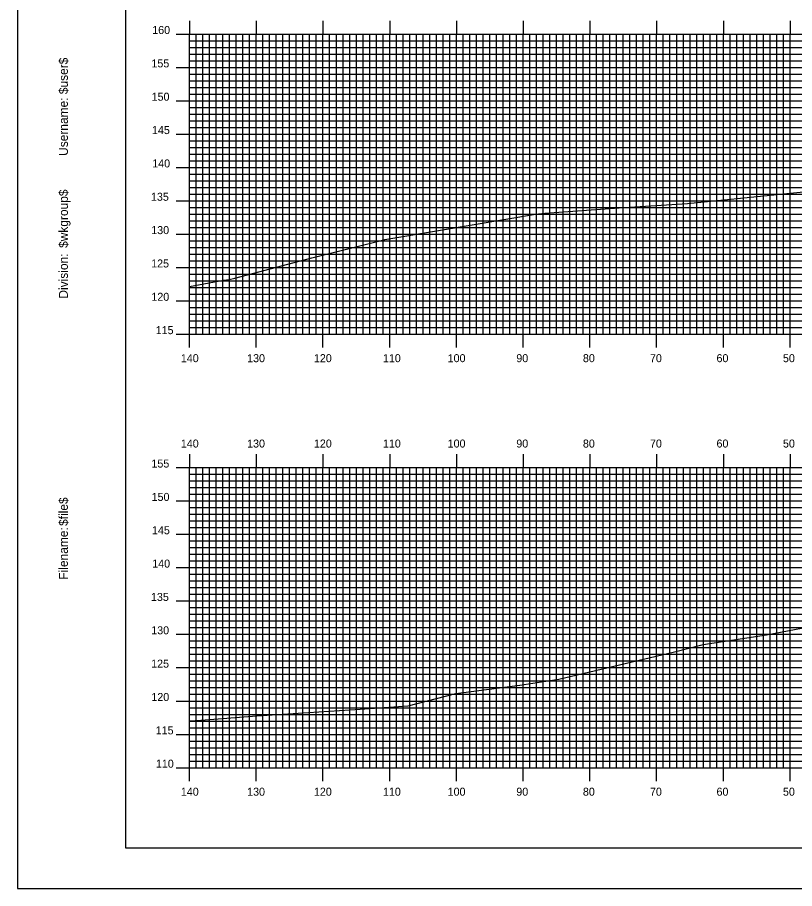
# Model space of a CAD drawing. Extents: x 1782647 to 1782990, y 442591 to 442811.
# Drawn here: x 1782647.2 to 1782763.6, y 442590.5 to 442721.2 of the extents above; entities that cross this region are included whole.
import ezdxf

# ---------------------------------------------------------------- set-up
doc = ezdxf.new("R2010")
doc.units = 0
for name, color, linetype in [('BORDER', 7, 'Continuous'), ('H_V ANNOTATION', 7, 'Continuous'), ('MAJOR', 7, 'Continuous'), ('MINOR', 7, 'Continuous'), ('PLOT BOUNDARY', 7, 'Continuous'), ('S_Roadway_Centerline', 7, 'Continuous')]:
    doc.layers.add(name, color=color, linetype=linetype)

msp = doc.modelspace()

# ---------------------------------------------------------------- linework, layer by layer
at = {"layer": 'BORDER'}
msp.add_lwpolyline([(1782663.35, 442596.67), (1782983.35, 442596.67), (1782983.35, 442806.67), (1782663.35, 442806.67)], close=True, dxfattribs=at)
at = {"layer": 'MAJOR'}
for p, q in [((1782672.95, 442720.67), (1782672.95, 442718.67)), ((1782682.95, 442720.67), (1782682.95, 442718.67)), ((1782692.95, 442720.67), (1782692.95, 442718.67)), ((1782702.95, 442720.67), (1782702.95, 442718.67)), ((1782712.95, 442720.67), (1782712.95, 442718.67)), ((1782722.95, 442720.67), (1782722.95, 442718.67)), ((1782732.95, 442720.67), (1782732.95, 442718.67)), ((1782742.95, 442720.67), (1782742.95, 442718.67)), ((1782752.95, 442720.67), (1782752.95, 442718.67)), ((1782762.95, 442720.67), (1782762.95, 442718.67)), ((1782670.94, 442718.67), (1782672.95, 442718.67)), ((1782672.95, 442718.67), (1782952.95, 442718.67)), ((1782672.95, 442673.67), (1782672.95, 442718.67)), ((1782672.95, 442673.67), (1782672.95, 442718.67)), ((1782672.95, 442718.67), (1782952.95, 442718.67)), ((1782682.95, 442673.67), (1782682.95, 442718.67)), ((1782692.95, 442673.67), (1782692.95, 442718.67)), ((1782702.95, 442673.67), (1782702.95, 442718.67)), ((1782712.95, 442673.67), (1782712.95, 442718.67)), ((1782722.95, 442673.67), (1782722.95, 442718.67)), ((1782732.95, 442673.67), (1782732.95, 442718.67)), ((1782742.95, 442673.67), (1782742.95, 442718.67)), ((1782752.95, 442673.67), (1782752.95, 442718.67)), ((1782762.95, 442673.67), (1782762.95, 442718.67)), ((1782670.94, 442713.67), (1782672.95, 442713.67)), ((1782672.95, 442713.67), (1782952.95, 442713.67)), ((1782670.94, 442708.67), (1782672.95, 442708.67)), ((1782672.95, 442708.67), (1782952.95, 442708.67)), ((1782670.94, 442703.67), (1782672.95, 442703.67)), ((1782672.95, 442703.67), (1782952.95, 442703.67)), ((1782670.94, 442698.67), (1782672.95, 442698.67)), ((1782672.95, 442698.67), (1782952.95, 442698.67)), ((1782670.94, 442693.67), (1782672.95, 442693.67)), ((1782672.95, 442693.67), (1782952.95, 442693.67)), ((1782670.94, 442688.67), (1782672.95, 442688.67)), ((1782672.95, 442688.67), (1782952.95, 442688.67)), ((1782670.94, 442683.67), (1782672.95, 442683.67)), ((1782672.95, 442683.67), (1782952.95, 442683.67)), ((1782670.94, 442678.67), (1782672.95, 442678.67)), ((1782672.95, 442678.67), (1782952.95, 442678.67)), ((1782670.94, 442673.67), (1782672.95, 442673.67)), ((1782672.95, 442673.67), (1782952.95, 442673.67)), ((1782672.95, 442673.67), (1782952.95, 442673.67)), ((1782672.95, 442671.66), (1782672.95, 442673.67)), ((1782682.95, 442671.66), (1782682.95, 442673.67)), ((1782692.95, 442671.66), (1782692.95, 442673.67)), ((1782702.95, 442671.66), (1782702.95, 442673.67)), ((1782712.95, 442671.66), (1782712.95, 442673.67)), ((1782722.95, 442671.66), (1782722.95, 442673.67)), ((1782732.95, 442671.66), (1782732.95, 442673.67)), ((1782742.95, 442671.66), (1782742.95, 442673.67)), ((1782752.95, 442671.66), (1782752.95, 442673.67)), ((1782762.95, 442671.66), (1782762.95, 442673.67)), ((1782672.95, 442655.67), (1782672.95, 442653.67)), ((1782682.95, 442655.67), (1782682.95, 442653.67)), ((1782692.95, 442655.67), (1782692.95, 442653.67)), ((1782702.95, 442655.67), (1782702.95, 442653.67)), ((1782712.95, 442655.67), (1782712.95, 442653.67)), ((1782722.95, 442655.67), (1782722.95, 442653.67)), ((1782732.95, 442655.67), (1782732.95, 442653.67)), ((1782742.95, 442655.67), (1782742.95, 442653.67)), ((1782752.95, 442655.67), (1782752.95, 442653.67)), ((1782762.95, 442655.67), (1782762.95, 442653.67)), ((1782670.94, 442653.67), (1782672.95, 442653.67)), ((1782672.95, 442653.67), (1782952.95, 442653.67)), ((1782672.95, 442608.67), (1782672.95, 442653.67)), ((1782672.95, 442608.67), (1782672.95, 442653.67)), ((1782672.95, 442653.67), (1782952.95, 442653.67)), ((1782682.95, 442608.67), (1782682.95, 442653.67)), ((1782692.95, 442608.67), (1782692.95, 442653.67)), ((1782702.95, 442608.67), (1782702.95, 442653.67)), ((1782712.95, 442608.67), (1782712.95, 442653.67)), ((1782722.95, 442608.67), (1782722.95, 442653.67)), ((1782732.95, 442608.67), (1782732.95, 442653.67)), ((1782742.95, 442608.67), (1782742.95, 442653.67)), ((1782752.95, 442608.67), (1782752.95, 442653.67)), ((1782762.95, 442608.67), (1782762.95, 442653.67)), ((1782670.94, 442648.67), (1782672.95, 442648.67)), ((1782672.95, 442648.67), (1782952.95, 442648.67)), ((1782670.94, 442643.67), (1782672.95, 442643.67)), ((1782672.95, 442643.67), (1782952.95, 442643.67)), ((1782670.94, 442638.67), (1782672.95, 442638.67)), ((1782672.95, 442638.67), (1782952.95, 442638.67)), ((1782670.94, 442633.67), (1782672.95, 442633.67)), ((1782672.95, 442633.67), (1782952.95, 442633.67)), ((1782670.94, 442628.67), (1782672.95, 442628.67)), ((1782672.95, 442628.67), (1782952.95, 442628.67)), ((1782670.94, 442623.67), (1782672.95, 442623.67)), ((1782672.95, 442623.67), (1782952.95, 442623.67)), ((1782670.94, 442618.67), (1782672.95, 442618.67)), ((1782672.95, 442618.67), (1782952.95, 442618.67)), ((1782670.94, 442613.67), (1782672.95, 442613.67)), ((1782672.95, 442613.67), (1782952.95, 442613.67)), ((1782670.94, 442608.67), (1782672.95, 442608.67)), ((1782672.95, 442608.67), (1782952.95, 442608.67)), ((1782672.95, 442608.67), (1782952.95, 442608.67)), ((1782672.95, 442606.66), (1782672.95, 442608.67)), ((1782682.95, 442606.66), (1782682.95, 442608.67)), ((1782692.95, 442606.66), (1782692.95, 442608.67)), ((1782702.95, 442606.66), (1782702.95, 442608.67)), ((1782712.95, 442606.66), (1782712.95, 442608.67)), ((1782722.95, 442606.66), (1782722.95, 442608.67)), ((1782732.95, 442606.66), (1782732.95, 442608.67)), ((1782742.95, 442606.66), (1782742.95, 442608.67)), ((1782752.95, 442606.66), (1782752.95, 442608.67)), ((1782762.95, 442606.66), (1782762.95, 442608.67))]:
    msp.add_line(p, q, dxfattribs=at)
at = {"layer": 'MINOR'}
for p, q in [((1782673.95, 442673.67), (1782673.95, 442718.67)), ((1782674.95, 442673.67), (1782674.95, 442718.67)), ((1782675.95, 442673.67), (1782675.95, 442718.67)), ((1782676.95, 442673.67), (1782676.95, 442718.67)), ((1782677.95, 442673.67), (1782677.95, 442718.67)), ((1782678.95, 442673.67), (1782678.95, 442718.67)), ((1782679.95, 442673.67), (1782679.95, 442718.67)), ((1782680.95, 442673.67), (1782680.95, 442718.67)), ((1782681.95, 442673.67), (1782681.95, 442718.67)), ((1782683.95, 442673.67), (1782683.95, 442718.67)), ((1782684.95, 442673.67), (1782684.95, 442718.67)), ((1782685.95, 442673.67), (1782685.95, 442718.67)), ((1782686.95, 442673.67), (1782686.95, 442718.67)), ((1782687.95, 442673.67), (1782687.95, 442718.67)), ((1782688.95, 442673.67), (1782688.95, 442718.67)), ((1782689.95, 442673.67), (1782689.95, 442718.67)), ((1782690.95, 442673.67), (1782690.95, 442718.67)), ((1782691.95, 442673.67), (1782691.95, 442718.67)), ((1782693.95, 442673.67), (1782693.95, 442718.67)), ((1782694.95, 442673.67), (1782694.95, 442718.67)), ((1782695.95, 442673.67), (1782695.95, 442718.67)), ((1782696.95, 442673.67), (1782696.95, 442718.67)), ((1782697.95, 442673.67), (1782697.95, 442718.67)), ((1782698.95, 442673.67), (1782698.95, 442718.67)), ((1782699.95, 442673.67), (1782699.95, 442718.67)), ((1782700.95, 442673.67), (1782700.95, 442718.67)), ((1782701.95, 442673.67), (1782701.95, 442718.67)), ((1782703.95, 442673.67), (1782703.95, 442718.67)), ((1782704.95, 442673.67), (1782704.95, 442718.67)), ((1782705.95, 442673.67), (1782705.95, 442718.67)), ((1782706.95, 442673.67), (1782706.95, 442718.67)), ((1782707.95, 442673.67), (1782707.95, 442718.67)), ((1782708.95, 442673.67), (1782708.95, 442718.67)), ((1782709.95, 442673.67), (1782709.95, 442718.67)), ((1782710.95, 442673.67), (1782710.95, 442718.67)), ((1782711.95, 442673.67), (1782711.95, 442718.67)), ((1782713.95, 442673.67), (1782713.95, 442718.67)), ((1782714.95, 442673.67), (1782714.95, 442718.67)), ((1782715.95, 442673.67), (1782715.95, 442718.67)), ((1782716.95, 442673.67), (1782716.95, 442718.67)), ((1782717.95, 442673.67), (1782717.95, 442718.67)), ((1782718.95, 442673.67), (1782718.95, 442718.67)), ((1782719.95, 442673.67), (1782719.95, 442718.67)), ((1782720.95, 442673.67), (1782720.95, 442718.67)), ((1782721.95, 442673.67), (1782721.95, 442718.67)), ((1782723.95, 442673.67), (1782723.95, 442718.67)), ((1782724.95, 442673.67), (1782724.95, 442718.67)), ((1782725.95, 442673.67), (1782725.95, 442718.67)), ((1782726.95, 442673.67), (1782726.95, 442718.67)), ((1782727.95, 442673.67), (1782727.95, 442718.67)), ((1782728.95, 442673.67), (1782728.95, 442718.67)), ((1782729.95, 442673.67), (1782729.95, 442718.67)), ((1782730.95, 442673.67), (1782730.95, 442718.67)), ((1782731.95, 442673.67), (1782731.95, 442718.67)), ((1782733.95, 442673.67), (1782733.95, 442718.67)), ((1782734.95, 442673.67), (1782734.95, 442718.67)), ((1782735.95, 442673.67), (1782735.95, 442718.67)), ((1782736.95, 442673.67), (1782736.95, 442718.67)), ((1782737.95, 442673.67), (1782737.95, 442718.67)), ((1782738.95, 442673.67), (1782738.95, 442718.67)), ((1782739.95, 442673.67), (1782739.95, 442718.67)), ((1782740.95, 442673.67), (1782740.95, 442718.67)), ((1782741.95, 442673.67), (1782741.95, 442718.67)), ((1782743.95, 442673.67), (1782743.95, 442718.67)), ((1782744.95, 442673.67), (1782744.95, 442718.67)), ((1782745.95, 442673.67), (1782745.95, 442718.67)), ((1782746.95, 442673.67), (1782746.95, 442718.67)), ((1782747.95, 442673.67), (1782747.95, 442718.67)), ((1782748.95, 442673.67), (1782748.95, 442718.67)), ((1782749.95, 442673.67), (1782749.95, 442718.67)), ((1782750.95, 442673.67), (1782750.95, 442718.67)), ((1782751.95, 442673.67), (1782751.95, 442718.67)), ((1782753.95, 442673.67), (1782753.95, 442718.67)), ((1782754.95, 442673.67), (1782754.95, 442718.67)), ((1782755.95, 442673.67), (1782755.95, 442718.67)), ((1782756.95, 442673.67), (1782756.95, 442718.67)), ((1782757.95, 442673.67), (1782757.95, 442718.67)), ((1782758.95, 442673.67), (1782758.95, 442718.67)), ((1782759.95, 442673.67), (1782759.95, 442718.67)), ((1782760.95, 442673.67), (1782760.95, 442718.67)), ((1782761.95, 442673.67), (1782761.95, 442718.67)), ((1782672.95, 442717.67), (1782952.95, 442717.67)), ((1782672.95, 442717.67), (1782674.95, 442717.67)), ((1782672.95, 442716.67), (1782952.95, 442716.67)), ((1782672.95, 442716.67), (1782674.95, 442716.67)), ((1782672.95, 442715.67), (1782952.95, 442715.67)), ((1782672.95, 442715.67), (1782674.95, 442715.67)), ((1782672.95, 442714.67), (1782952.95, 442714.67)), ((1782672.95, 442714.67), (1782674.95, 442714.67)), ((1782672.95, 442712.67), (1782952.95, 442712.67)), ((1782672.95, 442712.67), (1782674.95, 442712.67)), ((1782672.95, 442711.67), (1782952.95, 442711.67)), ((1782672.95, 442711.67), (1782674.95, 442711.67)), ((1782672.95, 442710.67), (1782952.95, 442710.67)), ((1782672.95, 442710.67), (1782674.95, 442710.67)), ((1782672.95, 442709.67), (1782952.95, 442709.67)), ((1782672.95, 442709.67), (1782674.95, 442709.67)), ((1782672.95, 442707.67), (1782952.95, 442707.67)), ((1782672.95, 442707.67), (1782674.95, 442707.67)), ((1782672.95, 442706.67), (1782952.95, 442706.67)), ((1782672.95, 442706.67), (1782674.95, 442706.67)), ((1782672.95, 442705.67), (1782952.95, 442705.67)), ((1782672.95, 442705.67), (1782674.95, 442705.67)), ((1782672.95, 442704.67), (1782952.95, 442704.67)), ((1782672.95, 442704.67), (1782674.95, 442704.67)), ((1782672.95, 442702.67), (1782952.95, 442702.67)), ((1782672.95, 442702.67), (1782674.95, 442702.67)), ((1782672.95, 442701.67), (1782952.95, 442701.67)), ((1782672.95, 442701.67), (1782674.95, 442701.67)), ((1782672.95, 442700.67), (1782952.95, 442700.67)), ((1782672.95, 442700.67), (1782674.95, 442700.67)), ((1782672.95, 442699.67), (1782952.95, 442699.67)), ((1782672.95, 442699.67), (1782674.95, 442699.67)), ((1782672.95, 442697.67), (1782952.95, 442697.67)), ((1782672.95, 442697.67), (1782674.95, 442697.67)), ((1782672.95, 442696.67), (1782952.95, 442696.67)), ((1782672.95, 442696.67), (1782674.95, 442696.67)), ((1782672.95, 442695.67), (1782952.95, 442695.67)), ((1782672.95, 442695.67), (1782674.95, 442695.67)), ((1782672.95, 442694.67), (1782952.95, 442694.67)), ((1782672.95, 442694.67), (1782674.95, 442694.67)), ((1782672.95, 442692.67), (1782952.95, 442692.67)), ((1782672.95, 442692.67), (1782674.95, 442692.67)), ((1782672.95, 442691.67), (1782952.95, 442691.67)), ((1782672.95, 442691.67), (1782674.95, 442691.67)), ((1782672.95, 442690.67), (1782952.95, 442690.67)), ((1782672.95, 442690.67), (1782674.95, 442690.67)), ((1782672.95, 442689.67), (1782952.95, 442689.67)), ((1782672.95, 442689.67), (1782674.95, 442689.67)), ((1782672.95, 442687.67), (1782952.95, 442687.67)), ((1782672.95, 442687.67), (1782674.95, 442687.67)), ((1782672.95, 442686.67), (1782952.95, 442686.67)), ((1782672.95, 442686.67), (1782674.95, 442686.67)), ((1782672.95, 442685.67), (1782952.95, 442685.67)), ((1782672.95, 442685.67), (1782674.95, 442685.67)), ((1782672.95, 442684.67), (1782952.95, 442684.67)), ((1782672.95, 442684.67), (1782674.95, 442684.67)), ((1782672.95, 442682.67), (1782952.95, 442682.67)), ((1782672.95, 442682.67), (1782674.95, 442682.67)), ((1782672.95, 442681.67), (1782952.95, 442681.67)), ((1782672.95, 442681.67), (1782674.95, 442681.67)), ((1782672.95, 442680.67), (1782952.95, 442680.67)), ((1782672.95, 442680.67), (1782674.95, 442680.67)), ((1782672.95, 442679.67), (1782952.95, 442679.67)), ((1782672.95, 442679.67), (1782674.95, 442679.67)), ((1782672.95, 442677.67), (1782952.95, 442677.67)), ((1782672.95, 442677.67), (1782674.95, 442677.67)), ((1782672.95, 442676.67), (1782952.95, 442676.67)), ((1782672.95, 442676.67), (1782674.95, 442676.67)), ((1782672.95, 442675.67), (1782952.95, 442675.67)), ((1782672.95, 442675.67), (1782674.95, 442675.67)), ((1782672.95, 442674.67), (1782952.95, 442674.67)), ((1782672.95, 442674.67), (1782674.95, 442674.67)), ((1782672.95, 442652.67), (1782952.95, 442652.67)), ((1782672.95, 442652.67), (1782674.95, 442652.67)), ((1782673.95, 442608.67), (1782673.95, 442653.67)), ((1782674.95, 442608.67), (1782674.95, 442653.67)), ((1782675.95, 442608.67), (1782675.95, 442653.67)), ((1782676.95, 442608.67), (1782676.95, 442653.67)), ((1782677.95, 442608.67), (1782677.95, 442653.67)), ((1782678.95, 442608.67), (1782678.95, 442653.67)), ((1782679.95, 442608.67), (1782679.95, 442653.67)), ((1782680.95, 442608.67), (1782680.95, 442653.67)), ((1782681.95, 442608.67), (1782681.95, 442653.67)), ((1782683.95, 442608.67), (1782683.95, 442653.67)), ((1782684.95, 442608.67), (1782684.95, 442653.67)), ((1782685.95, 442608.67), (1782685.95, 442653.67)), ((1782686.95, 442608.67), (1782686.95, 442653.67)), ((1782687.95, 442608.67), (1782687.95, 442653.67)), ((1782688.95, 442608.67), (1782688.95, 442653.67)), ((1782689.95, 442608.67), (1782689.95, 442653.67)), ((1782690.95, 442608.67), (1782690.95, 442653.67)), ((1782691.95, 442608.67), (1782691.95, 442653.67)), ((1782693.95, 442608.67), (1782693.95, 442653.67)), ((1782694.95, 442608.67), (1782694.95, 442653.67)), ((1782695.95, 442608.67), (1782695.95, 442653.67)), ((1782696.95, 442608.67), (1782696.95, 442653.67)), ((1782697.95, 442608.67), (1782697.95, 442653.67)), ((1782698.95, 442608.67), (1782698.95, 442653.67)), ((1782699.95, 442608.67), (1782699.95, 442653.67)), ((1782700.95, 442608.67), (1782700.95, 442653.67)), ((1782701.95, 442608.67), (1782701.95, 442653.67)), ((1782703.95, 442608.67), (1782703.95, 442653.67)), ((1782704.95, 442608.67), (1782704.95, 442653.67)), ((1782705.95, 442608.67), (1782705.95, 442653.67)), ((1782706.95, 442608.67), (1782706.95, 442653.67)), ((1782707.95, 442608.67), (1782707.95, 442653.67)), ((1782708.95, 442608.67), (1782708.95, 442653.67)), ((1782709.95, 442608.67), (1782709.95, 442653.67)), ((1782710.95, 442608.67), (1782710.95, 442653.67)), ((1782711.95, 442608.67), (1782711.95, 442653.67)), ((1782713.95, 442608.67), (1782713.95, 442653.67)), ((1782714.95, 442608.67), (1782714.95, 442653.67)), ((1782715.95, 442608.67), (1782715.95, 442653.67)), ((1782716.95, 442608.67), (1782716.95, 442653.67)), ((1782717.95, 442608.67), (1782717.95, 442653.67)), ((1782718.95, 442608.67), (1782718.95, 442653.67)), ((1782719.95, 442608.67), (1782719.95, 442653.67)), ((1782720.95, 442608.67), (1782720.95, 442653.67)), ((1782721.95, 442608.67), (1782721.95, 442653.67)), ((1782723.95, 442608.67), (1782723.95, 442653.67)), ((1782724.95, 442608.67), (1782724.95, 442653.67)), ((1782725.95, 442608.67), (1782725.95, 442653.67)), ((1782726.95, 442608.67), (1782726.95, 442653.67)), ((1782727.95, 442608.67), (1782727.95, 442653.67)), ((1782728.95, 442608.67), (1782728.95, 442653.67)), ((1782729.95, 442608.67), (1782729.95, 442653.67)), ((1782730.95, 442608.67), (1782730.95, 442653.67)), ((1782731.95, 442608.67), (1782731.95, 442653.67)), ((1782733.95, 442608.67), (1782733.95, 442653.67)), ((1782734.95, 442608.67), (1782734.95, 442653.67)), ((1782735.95, 442608.67), (1782735.95, 442653.67)), ((1782736.95, 442608.67), (1782736.95, 442653.67)), ((1782737.95, 442608.67), (1782737.95, 442653.67)), ((1782738.95, 442608.67), (1782738.95, 442653.67)), ((1782739.95, 442608.67), (1782739.95, 442653.67)), ((1782740.95, 442608.67), (1782740.95, 442653.67)), ((1782741.95, 442608.67), (1782741.95, 442653.67)), ((1782743.95, 442608.67), (1782743.95, 442653.67)), ((1782744.95, 442608.67), (1782744.95, 442653.67)), ((1782745.95, 442608.67), (1782745.95, 442653.67)), ((1782746.95, 442608.67), (1782746.95, 442653.67)), ((1782747.95, 442608.67), (1782747.95, 442653.67)), ((1782748.95, 442608.67), (1782748.95, 442653.67)), ((1782749.95, 442608.67), (1782749.95, 442653.67)), ((1782750.95, 442608.67), (1782750.95, 442653.67)), ((1782751.95, 442608.67), (1782751.95, 442653.67)), ((1782753.95, 442608.67), (1782753.95, 442653.67)), ((1782754.95, 442608.67), (1782754.95, 442653.67)), ((1782755.95, 442608.67), (1782755.95, 442653.67)), ((1782756.95, 442608.67), (1782756.95, 442653.67)), ((1782757.95, 442608.67), (1782757.95, 442653.67)), ((1782758.95, 442608.67), (1782758.95, 442653.67)), ((1782759.95, 442608.67), (1782759.95, 442653.67)), ((1782760.95, 442608.67), (1782760.95, 442653.67)), ((1782761.95, 442608.67), (1782761.95, 442653.67)), ((1782672.95, 442651.67), (1782952.95, 442651.67)), ((1782672.95, 442651.67), (1782674.95, 442651.67)), ((1782672.95, 442650.67), (1782952.95, 442650.67)), ((1782672.95, 442650.67), (1782674.95, 442650.67)), ((1782672.95, 442649.67), (1782952.95, 442649.67)), ((1782672.95, 442649.67), (1782674.95, 442649.67)), ((1782672.95, 442647.67), (1782952.95, 442647.67)), ((1782672.95, 442647.67), (1782674.95, 442647.67)), ((1782672.95, 442646.67), (1782952.95, 442646.67)), ((1782672.95, 442646.67), (1782674.95, 442646.67)), ((1782672.95, 442645.67), (1782952.95, 442645.67)), ((1782672.95, 442645.67), (1782674.95, 442645.67)), ((1782672.95, 442644.67), (1782952.95, 442644.67)), ((1782672.95, 442644.67), (1782674.95, 442644.67)), ((1782672.95, 442642.67), (1782952.95, 442642.67)), ((1782672.95, 442642.67), (1782674.95, 442642.67)), ((1782672.95, 442641.67), (1782952.95, 442641.67)), ((1782672.95, 442641.67), (1782674.95, 442641.67)), ((1782672.95, 442640.67), (1782952.95, 442640.67)), ((1782672.95, 442640.67), (1782674.95, 442640.67)), ((1782672.95, 442639.67), (1782952.95, 442639.67)), ((1782672.95, 442639.67), (1782674.95, 442639.67)), ((1782672.95, 442637.67), (1782952.95, 442637.67)), ((1782672.95, 442637.67), (1782674.95, 442637.67)), ((1782672.95, 442636.67), (1782952.95, 442636.67)), ((1782672.95, 442636.67), (1782674.95, 442636.67)), ((1782672.95, 442635.67), (1782952.95, 442635.67)), ((1782672.95, 442635.67), (1782674.95, 442635.67)), ((1782672.95, 442634.67), (1782952.95, 442634.67)), ((1782672.95, 442634.67), (1782674.95, 442634.67)), ((1782672.95, 442632.67), (1782952.95, 442632.67)), ((1782672.95, 442632.67), (1782674.95, 442632.67)), ((1782672.95, 442631.67), (1782952.95, 442631.67)), ((1782672.95, 442631.67), (1782674.95, 442631.67)), ((1782672.95, 442630.67), (1782952.95, 442630.67)), ((1782672.95, 442630.67), (1782674.95, 442630.67)), ((1782672.95, 442629.67), (1782952.95, 442629.67)), ((1782672.95, 442629.67), (1782674.95, 442629.67)), ((1782672.95, 442627.67), (1782952.95, 442627.67)), ((1782672.95, 442627.67), (1782674.95, 442627.67)), ((1782672.95, 442626.67), (1782952.95, 442626.67)), ((1782672.95, 442626.67), (1782674.95, 442626.67)), ((1782672.95, 442625.67), (1782952.95, 442625.67)), ((1782672.95, 442625.67), (1782674.95, 442625.67)), ((1782672.95, 442624.67), (1782952.95, 442624.67)), ((1782672.95, 442624.67), (1782674.95, 442624.67)), ((1782672.95, 442622.67), (1782952.95, 442622.67)), ((1782672.95, 442622.67), (1782674.95, 442622.67)), ((1782672.95, 442621.67), (1782952.95, 442621.67)), ((1782672.95, 442621.67), (1782674.95, 442621.67)), ((1782672.95, 442620.67), (1782952.95, 442620.67)), ((1782672.95, 442620.67), (1782674.95, 442620.67)), ((1782672.95, 442619.67), (1782952.95, 442619.67)), ((1782672.95, 442619.67), (1782674.95, 442619.67)), ((1782672.95, 442617.67), (1782952.95, 442617.67)), ((1782672.95, 442617.67), (1782674.95, 442617.67)), ((1782672.95, 442616.67), (1782952.95, 442616.67)), ((1782672.95, 442616.67), (1782674.95, 442616.67)), ((1782672.95, 442615.67), (1782952.95, 442615.67)), ((1782672.95, 442615.67), (1782674.95, 442615.67)), ((1782672.95, 442614.67), (1782952.95, 442614.67)), ((1782672.95, 442614.67), (1782674.95, 442614.67)), ((1782672.95, 442612.67), (1782952.95, 442612.67)), ((1782672.95, 442612.67), (1782674.95, 442612.67)), ((1782672.95, 442611.67), (1782952.95, 442611.67)), ((1782672.95, 442611.67), (1782674.95, 442611.67)), ((1782672.95, 442610.67), (1782952.95, 442610.67)), ((1782672.95, 442610.67), (1782674.95, 442610.67)), ((1782672.95, 442609.67), (1782952.95, 442609.67)), ((1782672.95, 442609.67), (1782674.95, 442609.67))]:
    msp.add_line(p, q, dxfattribs=at)
at = {"layer": 'PLOT BOUNDARY'}
msp.add_lwpolyline([(1782647.16, 442590.55), (1782987.16, 442590.55), (1782987.16, 442810.55), (1782647.16, 442810.55)], close=True, dxfattribs=at)
at = {"layer": 'S_Roadway_Centerline'}
for points in [[(1782672.95, 442680.84), (1782678.05, 442681.79), (1782678.87, 442681.85), (1782679.73, 442682.05), (1782691.3, 442685.12), (1782701.86, 442687.75), (1782702.24, 442687.84), (1782710.86, 442689.31), (1782724.8, 442691.65), (1782726.2, 442691.79), (1782737.35, 442692.61), (1782747.58, 442693.27), (1782751.06, 442693.59), (1782771.92, 442695.7)], [(1782672.95, 442615.69), (1782674.63, 442615.81), (1782683.05, 442616.45), (1782698.54, 442617.46), (1782705.72, 442617.94), (1782712.85, 442619.79), (1782722.44, 442621.05), (1782728.3, 442621.95), (1782745.61, 442626.05), (1782749.9, 442627.15), (1782759.41, 442628.58), (1782769.9, 442630.59)]]:
    msp.add_lwpolyline(points, dxfattribs=at)

# ---------------------------------------------------------------- texts
at = {"layer": 'BORDER'}
for s, p in [('$user$', (1782654.72, 442709.65)), ('$user$', (1782654.72, 442709.65)), ('Username:', (1782654.72, 442700.4)), ('Username:', (1782654.72, 442700.4)), ('$wkgroup$', (1782654.72, 442686.6)), ('$wkgroup$', (1782654.72, 442686.6)), ('Division:', (1782654.72, 442679)), ('Division:', (1782654.72, 442679)), ('$file$', (1782654.72, 442644.92)), ('$file$', (1782654.72, 442644.92)), ('Filename:', (1782654.72, 442636.86)), ('Filename:', (1782654.72, 442636.86))]:
    msp.add_text(s, height=1.339, rotation=90, dxfattribs=at).set_placement(p)
at = {"layer": 'H_V ANNOTATION'}
for s, p in [('160', (1782667.36, 442718.67)), ('155', (1782667.24, 442713.67)), ('150', (1782667.27, 442708.67)), ('145', (1782667.32, 442703.67)), ('140', (1782667.36, 442698.67)), ('135', (1782667.17, 442693.67)), ('130', (1782667.21, 442688.67)), ('125', (1782667.2, 442683.67)), ('120', (1782667.23, 442678.67)), ('115', (1782667.88, 442673.67)), ('140', (1782671.65, 442669.47)), ('130', (1782681.58, 442669.47)), ('120', (1782691.59, 442669.47)), ('110', (1782701.93, 442669.47)), ('100', (1782711.63, 442669.47)), ('90', (1782721.92, 442669.47)), ('80', (1782731.9, 442669.47)), ('70', (1782741.95, 442669.47)), ('60', (1782751.92, 442669.47)), ('50', (1782761.88, 442669.47)), ('140', (1782671.65, 442656.67)), ('130', (1782681.58, 442656.67)), ('120', (1782691.59, 442656.67)), ('110', (1782701.93, 442656.67)), ('100', (1782711.63, 442656.67)), ('90', (1782721.92, 442656.67)), ('80', (1782731.9, 442656.67)), ('70', (1782741.95, 442656.67)), ('60', (1782751.92, 442656.67)), ('50', (1782761.88, 442656.67)), ('155', (1782667.24, 442653.67)), ('150', (1782667.27, 442648.67)), ('145', (1782667.32, 442643.67)), ('140', (1782667.36, 442638.67)), ('135', (1782667.17, 442633.67)), ('130', (1782667.21, 442628.67)), ('125', (1782667.2, 442623.67)), ('120', (1782667.23, 442618.67)), ('115', (1782667.88, 442613.67)), ('110', (1782667.91, 442608.67)), ('140', (1782671.65, 442604.47)), ('130', (1782681.58, 442604.47)), ('120', (1782691.59, 442604.47)), ('110', (1782701.93, 442604.47)), ('100', (1782711.63, 442604.47)), ('90', (1782721.92, 442604.47)), ('80', (1782731.9, 442604.47)), ('70', (1782741.95, 442604.47)), ('60', (1782751.92, 442604.47)), ('50', (1782761.88, 442604.47))]:
    msp.add_text(s, height=1.2, dxfattribs=at).set_placement(p)
at = {"layer": 'MAJOR'}
for p in [(1782672.94, 442673.67), (1782672.94, 442608.67)]:
    msp.add_text('-', height=0.012, dxfattribs=at).set_placement(p)

doc.saveas('drawing.dxf')
